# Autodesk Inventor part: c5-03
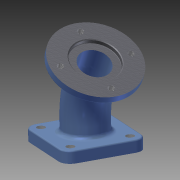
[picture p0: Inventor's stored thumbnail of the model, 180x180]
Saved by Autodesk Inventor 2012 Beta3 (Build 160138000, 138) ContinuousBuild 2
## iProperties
Created: 2010-11
Part Number: c5-03
Material: Cast Iron
Document SubType Name: Modeling
Designer: Beta-8540w
Density: 7.25 g/cm^3
Mass: 2169.78 g
Surface Area: 714.306 cm^2
Volume: 299.28 cm^3
Author: Beta-8540w
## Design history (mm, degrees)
sketch "Sketch1"
  geometry: L1 (50, 50)-(50, -50); L2 (50, -50)-(-50, -50); L3 (-50, -50)-(-50, 50); L4 (-50, 50)-(50, 50); C1 r 28 at (0, 0); C2 r 20 at (0, 0); 2 further points
  constraints: 8 end point, 3 coincident, 2 centre point, 1 horizontal, 9 other
  dimensions: "d0" = 100 distance of L3.end L1.start; "d8" = 8 radial gap between concentric circles of C1 C2; "d17" = 40 diameter of C2
extrude "Extrusion1" new body sketch "Sketch1" distance "d1" = 15; taper "d2" = 0 deg
sketch "Sketch2"
  geometry: L1 (0, 0)-(0, 30); L2 (-13.397, 80)-(-28.397, 105.981); A1 r 100 centre (-100, 30) between (0, 30) and (-13.397, 80)
  constraints: 4 end point, 2 point on circle, 2 tangent, 1 centre point, 1 vertical
  dimensions: "d3" = 30 distance of L1.start L1.end; "d4" = 30 distance of L2.start L2.end; "d5" = 150 deg angle of L1 L2; "d6" = 100 radius of A1
workplane "Work Plane1"
sketch "Sketch3"
  geometry: C1 r 55 at (0, 0); 2 further points
  constraints: 1 centre point, 1 coincident
  dimensions: "d9" = 110 diameter of C1
extrude "Extrusion2" join sketch "Sketch3" distance "d10" = 10; taper "d11" = 0 deg
sweep "Sweep1" dims "d12" = 0
sweep "Sweep2" dims "d13" = 0
fillet "Fillet1" dims "d14" = 14, "d15" = 6, "d16" = 2
hole "Hole1" diameter "d20" = 11; stored, may be unused: countersink angle "d24" = 90 deg, drill point angle "d26" = 118 deg; dims "d18" = 10, "d19" = 10, "d21" = 6, "d22" = 20, "d23" = 2, "d25" = 8
hole "Hole2" diameter "d29" = 11; stored, may be unused: countersink angle "d33" = 90 deg, drill point angle "d35" = 118 deg; dims "d27" = 10, "d28" = 10, "d30" = 6, "d31" = 20, "d32" = 2, "d34" = 8
hole "Hole3" diameter "d38" = 11; stored, may be unused: countersink angle "d42" = 90 deg, drill point angle "d44" = 118 deg; dims "d36" = 10, "d37" = 10, "d39" = 6, "d40" = 20, "d41" = 2, "d43" = 8
hole "Hole4" diameter "d47" = 11; stored, may be unused: countersink angle "d51" = 90 deg, drill point angle "d53" = 118 deg; dims "d45" = 10, "d46" = 10, "d48" = 6, "d49" = 20, "d50" = 2, "d52" = 8
sketch "Sketch4" dims "d54" = 85
  geometry: L1 (0, 42.5)-(42.5, 0); L2 (42.5, 0)-(0, -42.5); L3 (0, -42.5)-(-42.5, 0); L4 (-42.5, 0)-(0, 42.5); C1 r 55 at (0, 0) reference; 3 further points
  constraints: 8 end point, 2 coincident, 1 vertical alignment, 11 other
hole "Hole5" sketch "Sketch4" at (0, 42.5), (42.5, 0), (0, -42.5), (-42.5, 0) diameter "d55" = 8.376; stored, may be unused: countersink angle "d59" = 90 deg, drill point angle "d61" = 118 deg; dims "d56" = 6, "d57" = 20, "d58" = 2, "d60" = 8
sketch "Sketch5"
  geometry: C1 r 55 at (0, 0) reference; C2 r 30 at (0, 0); 1 further point
  constraints: 1 centre point, 1 coincident
  dimensions: "d62" = 60 diameter of C2
extrude "Extrusion3" cut sketch "Sketch5" distance "d63" = 6; taper "d64" = 0 deg
sketch "Sketch6"
  geometry: C1 r 20 at (0, 0) reference; C2 r 30 at (0, 0); C3 r 33 at (0, 0)
  constraints: 2 centre point, 1 coincident
  dimensions: "d65" = 60 diameter of C2; "d66" = 3 radial gap between concentric circles of C3 C2
extrude "Extrusion4" cut sketch "Sketch6" distance "d67" = 3; taper "d68" = 0 deg
fillet "Fillet2" dims "d69" = 0.5
chamfer "Chamfer1" distance "d70" = 2; stored, may be unused: second distance "d71" = 2, angle "d72" = 45 deg
chamfer "Chamfer2" distance "d73" = 1; stored, may be unused: second distance "d74" = 2, angle "d75" = 45 deg
fillet "Fillet3" dims "d76" = 0.5
body "Solid1"
